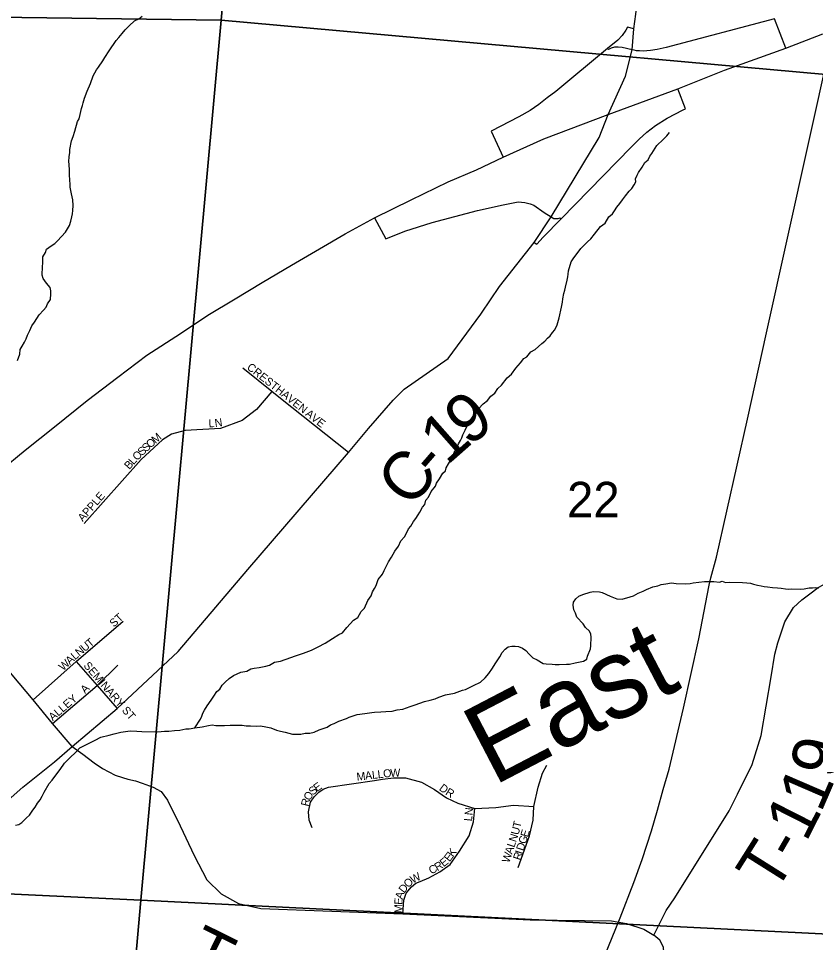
# Model space of a CAD drawing. Extents: x 1310247 to 1552180, y 377264 to 706493.
# Drawn here: x 1428492 to 1433472, y 489060 to 494835 of the extents above; entities that cross this region are included whole.
import ezdxf

# ---------------------------------------------------------------- set-up
doc = ezdxf.new("R2010")
doc.units = 0
for name, color, linetype in [('GM_X_County_Road', 7, 'Continuous'), ('GM_X_County_Road_Text', 7, 'Continuous'), ('GM_X_Interchange_Ramps', 7, 'Continuous'), ('GM_X_Interstate_Route', 7, 'Continuous'), ('GM_X_Minor_River', 7, 'Continuous'), ('GM_X_Minor_River_Text', 7, 'Continuous'), ('GM_X_Rail_Line', 7, 'Continuous'), ('GM_X_Section', 7, 'Continuous'), ('GM_X_Section_Text', 7, 'Continuous'), ('GM_X_Township_Road', 7, 'Continuous'), ('GM_X_Township_Road_Text', 7, 'Continuous'), ('GM_X_Township_Subdivision', 7, 'Continuous'), ('GM_X_Township_Subdivision_Text', 7, 'Continuous')]:
    doc.layers.add(name, color=color, linetype=linetype)

msp = doc.modelspace()

# ---------------------------------------------------------------- linework, layer by layer
at = {"layer": 'GM_X_County_Road'}
for points in [[(1431381.6, 492987.5), (1431385.2, 492992.3), (1431497.9, 493159), (1431713.4, 493434.6), (1431820.6, 493596.1), (1432120.9, 494091.1), (1432177.2, 494235.8), (1432285.4, 494474.8), (1432325.4, 494638.3), (1432336.7, 494770.6), (1432349.4, 494862.8), (1432380, 495160.6), (1432473.4, 496205.1), (1432525.8, 496791), (1432540.5, 496955.1), (1432582.1, 497292.2), (1432617.5, 497731.2), (1432712.9, 500020.8)], [(1429724.6, 491155.6), (1429924.8, 491390.6), (1430553.7, 492122.3), (1430678.1, 492272.1), (1430832.5, 492450.4), (1430902, 492518.3), (1431177.2, 492710), (1431381.6, 492987.5)], [(1428071.5, 488432.1), (1428071.5, 488432.1), (1428109.7, 488932), (1428113, 489124.6), (1428157.6, 489517.4), (1428185.3, 489642.2), (1428252.3, 489770.7), (1428370.4, 489902.4), (1428519, 490030.4), (1428716.9, 490189.5), (1428826.6, 490284.9), (1429108.1, 490523.8), (1429489.4, 490879.6), (1429724.6, 491155.6)]]:
    msp.add_lwpolyline(points, dxfattribs=at)
at = {"layer": 'GM_X_Interchange_Ramps'}
for points in [[(1433286.5, 494649.5), (1433214.7, 494832.9), (1432537.7, 494652.8), (1432483.3, 494640.6), (1432440.2, 494634.7), (1432394.3, 494631.6), (1432372.6, 494631.7), (1432353.3, 494633.2), (1432338.7, 494636.7), (1432325.4, 494638.3)], [(1432336.7, 494770.6), (1432296.1, 494780.5), (1432287.7, 494761.4), (1432264.8, 494727.5), (1432235.9, 494699.2), (1432173.1, 494647.1), (1431848.9, 494378.4), (1431794.6, 494338.9), (1431742.8, 494298.3), (1431688, 494260.4), (1431618.6, 494219.3), (1431444.5, 494130.2), (1431520.9, 493968.9)], [(1432325.4, 494638.3), (1432264.3, 494653.2), (1432237.8, 494656.2), (1432216.2, 494654.6), (1432196.1, 494648.8), (1432178.4, 494640.7), (1432173.1, 494647.1)], [(1431713.4, 493434.6), (1431730, 493423.8), (1431769.6, 493467.4), (1431881.7, 493582.3), (1432319.1, 494031), (1432370.4, 494080.3), (1432418.5, 494123.7), (1432471.5, 494165.7), (1432545.2, 494211.9), (1432645.1, 494263.5), (1432660.4, 494270.3), (1432610.9, 494395.8)], [(1430717.3, 493588.9), (1430787.5, 493457.1), (1430906.9, 493504.8), (1431077.2, 493559.6), (1431360.9, 493635.5), (1431520.8, 493669.6), (1431615, 493688.8), (1431656.5, 493685.2), (1431688.7, 493676.9), (1431712.7, 493667.3), (1431776.8, 493622.6), (1431820.6, 493596.1)], [(1431820.6, 493596.1), (1431837.3, 493585.9), (1431846.2, 493584.1), (1431856.5, 493584.3), (1431864.4, 493585.1), (1431874.6, 493589.2), (1431881.7, 493582.3)]]:
    msp.add_lwpolyline(points, dxfattribs=at)
at = {"layer": 'GM_X_Interstate_Route'}
for points in [[(1432177.2, 494235.8), (1432610.9, 494395.8), (1432903.4, 494511.1), (1433286.5, 494649.5), (1433516.8, 494739.6)], [(1428377.8, 492008.3), (1428533.6, 492136.5), (1428717.5, 492282.4), (1428921.8, 492448.1), (1429111.8, 492594), (1429293.7, 492729.9), (1429503.6, 492865.5), (1429675.2, 492981.5), (1429846.6, 493083.5), (1430014, 493185.5), (1430197.6, 493293.4), (1430373, 493395.3), (1430532.3, 493489.5), (1430717.3, 493588.9), (1430945.3, 493700.6), (1431177, 493813.8), (1431354.1, 493889.7), (1431520.9, 493968.9), (1431774.9, 494082.7), (1432177.2, 494235.8)]]:
    msp.add_lwpolyline(points, dxfattribs=at)
at = {"layer": 'GM_X_Minor_River'}
for points in [[(1428486, 492698.5), (1428500.8, 492736.3), (1428503.4, 492766.4), (1428515.8, 492786.2), (1428530.3, 492812), (1428540.7, 492831.9), (1428549.1, 492855.8), (1428563.7, 492885.6), (1428576.3, 492913.5), (1428592.7, 492937.2), (1428621.6, 492982.8), (1428648.1, 493012.4), (1428664.5, 493030.1), (1428672.9, 493052), (1428691.4, 493077.7), (1428694.1, 493113.8), (1428694.5, 493131.9), (1428689, 493154.1), (1428667.6, 493180.7), (1428646.2, 493209.2), (1428640.6, 493231.4), (1428641.7, 493285.6), (1428644.1, 493305.7), (1428645, 493345.8), (1428661.5, 493371.6), (1428667.9, 493393.5), (1428696.3, 493415), (1428718.5, 493428.6), (1428734.8, 493446.3), (1428761.3, 493471.9), (1428785.8, 493499.5), (1428810.6, 493541.2), (1428819.2, 493569.1), (1428825.7, 493595.1), (1428830.1, 493615.1), (1428832.5, 493635.1), (1428833.2, 493667.2), (1428831.9, 493701.4), (1428822.7, 493739.7), (1428815.5, 493780), (1428814, 493802.2), (1428812.4, 493822.3), (1428811.2, 493860.5), (1428809.7, 493886.6), (1428808.4, 493922.8), (1428806.8, 493940.9), (1428809.4, 493970.9), (1428811.9, 493997), (1428812.3, 494015.1), (1428823.4, 494071), (1428833.9, 494096.9), (1428844.6, 494130.9), (1428859.8, 494190.8), (1428870.2, 494208.6), (1428876.7, 494234.6), (1428885.4, 494272.6), (1428891.8, 494290.5), (1428896.2, 494308.5), (1428904.7, 494336.5), (1428921.6, 494380.3), (1428942.5, 494428), (1428959.5, 494475.9), (1428980.2, 494513.6), (1428992.5, 494531.4), (1429019.3, 494571), (1429031.7, 494590.9), (1429058.5, 494632.5), (1429101.7, 494697.8), (1429118.1, 494715.6), (1429140.5, 494741.2), (1429158.9, 494762.9), (1429183.4, 494788.5), (1429216, 494820), (1429244.2, 494833.5), (1429264.5, 494849.1)], [(1431796.6, 492836.5), (1431814.9, 492852.2), (1431829.3, 492872), (1431843.6, 492889.7), (1431858.2, 492919.5), (1431871, 492963.5), (1431884.4, 493031.5), (1431891, 493061.4), (1431893.5, 493083.5), (1431900.1, 493115.5), (1431906.5, 493137.4), (1431908.9, 493155.5), (1431919.8, 493199.4), (1431924.2, 493219.4), (1431926.5, 493237.4), (1431928.9, 493257.5), (1431946.1, 493313.3), (1431962.6, 493339.1), (1431989.2, 493374.7), (1432005.7, 493398.4), (1432046.4, 493439.8), (1432068.8, 493457.4), (1432091.3, 493487), (1432128.2, 493534.5), (1432156.6, 493556), (1432181.4, 493595.6), (1432203.7, 493613.2), (1432216.1, 493633), (1432230.5, 493654.8), (1432248.9, 493678.5), (1432265.4, 493702.3), (1432283.9, 493726), (1432308.4, 493755.6), (1432324.7, 493773.4), (1432339.2, 493795.1), (1432349.5, 493815), (1432347.9, 493833.1), (1432358.3, 493855), (1432366.7, 493872.9), (1432389.3, 493906.6), (1432405.9, 493934.3), (1432426.2, 493952), (1432436.6, 493973.8), (1432449, 493991.7), (1432479.9, 494041.2), (1432520.6, 494078.5), (1432543, 494102.2), (1432559.4, 494121.9)], [(1429593.1, 490402.2), (1429630.1, 490455.6), (1429636.5, 490475.6), (1429642.9, 490493.5), (1429653.2, 490511.4), (1429671.8, 490539.1), (1429696.4, 490574.7), (1429712.9, 490600.5), (1429731.5, 490628.2), (1429749.7, 490643.9), (1429764.2, 490667.7), (1429782.6, 490687.4), (1429809, 490711), (1429835.3, 490728.5), (1429881.6, 490749.6), (1429917.7, 490756.9), (1429944, 490770.4), (1429964, 490774), (1429996, 490779.4), (1430038.1, 490786.5), (1430060.2, 490794.1), (1430092.5, 490811.5), (1430128.6, 490818.8), (1430192.9, 490841.5), (1430223.1, 490851), (1430273.3, 490868), (1430323.6, 490887), (1430364, 490908.3), (1430408.4, 490931.5), (1430452.9, 490960.6), (1430493.3, 490985.9), (1430517.4, 490995.5), (1430544.1, 491029), (1430584.9, 491074.4), (1430611.2, 491091.9), (1430634, 491129.6), (1430654.3, 491149.2), (1430675.3, 491197), (1430695.8, 491226.7), (1430704.3, 491252.6), (1430716.7, 491272.5), (1430727.1, 491292.3), (1430739.8, 491328.2), (1430766.5, 491361.8), (1430776.9, 491385.7), (1430789.4, 491409.5), (1430804, 491439.3), (1430822.5, 491469.1), (1430843.3, 491506.8), (1430865.8, 491536.5), (1430880.5, 491570.3), (1430903, 491595.9), (1430913.3, 491613.8), (1430927.9, 491645.6), (1430944.3, 491663.3), (1430960.8, 491691.1), (1430975.2, 491710.9), (1430989.6, 491732.7), (1430999.9, 491750.5), (1431016.5, 491780.3), (1431030.8, 491798.1), (1431037.4, 491824.1), (1431053.7, 491843.8), (1431070.4, 491879.6), (1431097.1, 491913.2), (1431103.4, 491931.1), (1431121.9, 491958.9), (1431142.6, 491992.6), (1431160.9, 492008.3), (1431163.3, 492026.3), (1431194.2, 492075.8), (1431206.6, 492097.7), (1431215.1, 492121.6), (1431225.4, 492139.5), (1431242.2, 492177.3), (1431254.6, 492197.1), (1431262.9, 492215), (1431269.3, 492232.9), (1431281.9, 492262.8), (1431302.6, 492302.5), (1431333.5, 492350.1), (1431362, 492377.6), (1431366.4, 492395.6), (1431395, 492427.1), (1431423.3, 492446.6), (1431443.9, 492474.3), (1431468.2, 492493.9), (1431486.8, 492521.6), (1431509.2, 492543.2), (1431546, 492588.6), (1431572.4, 492612.2), (1431599.2, 492649.8), (1431627.8, 492683.3), (1431650.3, 492709), (1431668.5, 492720.7), (1431693.1, 492752.3), (1431719.3, 492765.8), (1431741.7, 492785.4), (1431762, 492803.1), (1431780.3, 492818.8), (1431796.6, 492836.5)], [(1431430.5, 490741.5), (1431453.2, 490775.2), (1431469.7, 490801), (1431498.6, 490846.5), (1431513.1, 490872.3), (1431533.5, 490894), (1431551.7, 490907.7), (1431573.8, 490913.2), (1431595.7, 490912.8), (1431615.6, 490910.4), (1431641.4, 490899.8), (1431661, 490885.3), (1431682.5, 490862.8), (1431706, 490840.2), (1431733.7, 490827.6), (1431771.2, 490804.7), (1431789.1, 490802.3), (1431827, 490799.5), (1431844.9, 490797.2), (1431870.9, 490798.6), (1431916.8, 490799.7), (1431934.8, 490799.3), (1431970.9, 490808.6), (1432023, 490819.6), (1432043.2, 490831.2), (1432047.6, 490849.2), (1432066.5, 490895), (1432068.9, 490915), (1432070, 490969.2), (1432068.3, 490987.3), (1432058.7, 491005.6), (1432035.2, 491028.2), (1432019.8, 491052.6), (1431980.7, 491093.6), (1431971.2, 491117.9), (1431961.7, 491140.1), (1431958.2, 491168.3), (1431960.6, 491186.4), (1431975, 491208.1), (1431993.3, 491223.8), (1432017.5, 491235.4), (1432063.7, 491250.5), (1432085.7, 491254), (1432121.6, 491251.3), (1432139.5, 491246.9), (1432188.9, 491223.8), (1432230.5, 491208.9), (1432264.4, 491206.1), (1432314.6, 491221.2), (1432334.7, 491226.8), (1432363, 491244.3), (1432395.2, 491255.6), (1432415.4, 491267.3), (1432455.6, 491282.5), (1432485.7, 491289.9), (1432507.8, 491297.5), (1432535.8, 491300.9), (1432571.9, 491308.2), (1432601.8, 491303.6), (1432659.6, 491302.4), (1432689.6, 491303.8), (1432707.7, 491307.4), (1432777.7, 491316), (1432795.7, 491315.6), (1432813.7, 491317.2), (1432835.6, 491316.8), (1432871.4, 491312), (1432889.5, 491317.7), (1432909.4, 491311.2), (1432933.3, 491312.7), (1433015.1, 491311), (1433043, 491308.5), (1433065, 491306), (1433084.8, 491299.5), (1433108.6, 491293), (1433132.5, 491288.5), (1433150.4, 491286.1), (1433172.3, 491283.7), (1433202.1, 491279), (1433234, 491276.4), (1433257.9, 491273.8), (1433283.8, 491271.3), (1433305.7, 491268.8), (1433323.7, 491270.5), (1433377.6, 491269.4), (1433401.6, 491270.9), (1433431.7, 491276.3), (1433453.6, 491277.8), (1433471.6, 491279.5), (1433491.6, 491277)], [(1428472.9, 489794.8), (1428494.9, 489798.4), (1428513.1, 489810.1), (1428541.7, 489839.6), (1428560, 489857.3), (1428582.6, 489887), (1428596.9, 489906.7), (1428611.4, 489930.5), (1428627.8, 489952.3), (1428640.2, 489974.1), (1428652.7, 490000), (1428683.7, 490053.5), (1428702.2, 490075.3), (1428730.9, 490114.8), (1428753.4, 490142.5), (1428780.2, 490182.1), (1428806.7, 490207.6), (1428855.6, 490256.8), (1428875.9, 490276.5), (1428916.3, 490297.7), (1428938.4, 490307.3), (1428970.7, 490324.7), (1429007.1, 490344), (1429059.2, 490357), (1429089.3, 490364.4), (1429131.5, 490375.6), (1429189.5, 490382.4), (1429231.4, 490381.6), (1429263.3, 490378.9), (1429363, 490376.8), (1429405.1, 490382), (1429431, 490381.4), (1429467, 490384.7), (1429501, 490388), (1429537.1, 490395.3), (1429559.1, 490396.8), (1429593.1, 490402.2), (1429639.2, 490409.2), (1429679.2, 490416.4), (1429701.3, 490420), (1429725.2, 490417.5), (1429779.1, 490416.4), (1429815.1, 490419.6), (1429888.9, 490418.1), (1429914.8, 490415.5), (1429940.7, 490415), (1429978.6, 490412.2), (1430004.6, 490413.7), (1430036.4, 490409), (1430068.2, 490402.3), (1430103.8, 490387.5), (1430129.7, 490381), (1430157.5, 490374.4), (1430181.3, 490367.8), (1430203.2, 490363.4), (1430257, 490362.2), (1430283.1, 490367.7), (1430313.1, 490369.1), (1430339.1, 490374.6), (1430371.4, 490390), (1430401.5, 490399.4), (1430421.6, 490407), (1430441.9, 490420.7), (1430464, 490428.2), (1430494.2, 490443.7), (1430540.5, 490460.8), (1430558.6, 490468.4), (1430608.9, 490485.5), (1430656.9, 490492.5), (1430699, 490497.7), (1430717, 490499.3), (1430756.9, 490502.5), (1430786.9, 490503.9), (1430826.9, 490507), (1430859, 490514.4), (1430893, 490519.7), (1430939.3, 490534.8), (1430971.4, 490546.2), (1431027.8, 490567.1), (1431063.8, 490574.4), (1431096, 490583.8), (1431118.1, 490593.4), (1431160.3, 490608.6), (1431216.5, 490619.5), (1431266.7, 490636.5), (1431284.8, 490642.1), (1431309, 490653.7), (1431335.2, 490667.2), (1431379.5, 490688.3), (1431408, 490713.9), (1431430.5, 490741.5)]]:
    msp.add_lwpolyline(points, dxfattribs=at)
at = {"layer": 'GM_X_Rail_Line'}
msp.add_lwpolyline([(1432127.7, 488911.9), (1432252.3, 489215.5), (1432336.2, 489435.2), (1432387.9, 489580.1), (1432446.1, 489759.1), (1432483.9, 489886.5), (1432520.8, 490016.6), (1432556.8, 490144), (1432646.4, 490524.2), (1432742.3, 490958), (1432806.9, 491293), (1432817.1, 491339.2), (1432853.1, 491469.3), (1433046, 492330.4), (1433166, 492869.4), (1433693.9, 495257.9)], dxfattribs=at)
at = {"layer": 'GM_X_Section'}
for points in [[(1430245.7, 500293), (1429758, 494823.6), (1424307.8, 494896.9), (1424746.1, 500303.3)], [(1430245.7, 500293), (1435471.2, 499726.6), (1434995.6, 494353), (1429758, 494823.6)], [(1429758, 494823.6), (1429255.8, 489324.6), (1423863.5, 489580.6), (1424307.8, 494896.9)], [(1429758, 494823.6), (1434995.6, 494353), (1434523.9, 489065.4), (1429255.8, 489324.6)], [(1423863.5, 489580.6), (1429255.8, 489324.6), (1428777.4, 483907.1), (1423391.5, 484184.8)], [(1434523.9, 489065.4), (1433994.3, 483685), (1428777.4, 483907.1), (1429255.8, 489324.6)]]:
    msp.add_lwpolyline(points, close=True, dxfattribs=at)
at = {"layer": 'GM_X_Township_Road'}
for points in [[(1428826.6, 490284.9), (1428705.1, 490428.4), (1428584, 490576.2), (1428453.1, 490733.5), (1428166.9, 491109.6), (1427837.1, 491506.3), (1427605.8, 491826.7), (1427337.7, 492126.1), (1427304, 492161.9)], [(1433194.5, 490721.5), (1433218.4, 490862.8), (1433236.7, 490932.4), (1433279.3, 491065), (1433335.2, 491155), (1433387.3, 491201.4), (1433435.6, 491239.3), (1433487.7, 491279.1), (1433581.5, 491328.4), (1433702.3, 491387), (1433702.7, 491387.2)], [(1432261.9, 487803.1), (1432291.4, 487909.7), (1432353.6, 488165.6), (1432478.8, 488765.2), (1432524.7, 488999.1), (1432522.4, 489030.8), (1432499.8, 489074.4), (1432460.7, 489105.6), (1432539.4, 489260.2), (1432592.1, 489340), (1432933, 489883.1), (1432984.5, 489987.3), (1433076.6, 490173.6), (1433132.5, 490354.6), (1433194.5, 490721.5)], [(1428826.6, 490284.9), (1428893.7, 490238), (1428965.2, 490182.9), (1429017.8, 490147.1), (1429095.8, 490107), (1429142.8, 490091.5), (1429174.5, 490081.5), (1429222.4, 490069.9), (1429264.8, 490056), (1429333.5, 490031.3), (1429383.7, 490003.5), (1429423.1, 489949.5), (1429460.7, 489873.6)], [(1429460.7, 489873.6), (1429484.8, 489825.2), (1429589, 489604.4), (1429669.3, 489452.4), (1429758, 489364.4), (1429867.6, 489303.7), (1430006.6, 489273.3), (1430892.7, 489239.4), (1431690, 489201.4), (1432196.2, 489195.6), (1432291.4, 489178.6), (1432399.6, 489144.6), (1432460.7, 489105.6)]]:
    msp.add_lwpolyline(points, dxfattribs=at)
at = {"layer": 'GM_X_Township_Subdivision'}
for points in [[(1430553.7, 492122.3), (1430129.7, 492460.4), (1430075.5, 492502.9), (1429892.8, 492650.1)], [(1430075.5, 492502.9), (1429979.3, 492391.9), (1429890.5, 492323.4), (1429753.6, 492271.6), (1429533.5, 492260.5), (1429448.4, 492236.4), (1429391, 492201.3), (1429257.8, 492079.2), (1428902.7, 491679.5)], [(1428584, 490576.2), (1428853, 490817), (1429146.2, 491068.3)], [(1428705.1, 490428.4), (1428983.4, 490667.1), (1429112.3, 490793.8)], [(1428853, 490817), (1428983.4, 490667.1), (1429108.1, 490523.8)], [(1431614.4, 489528.3), (1431684.8, 489726.8), (1431708.7, 489826), (1431711.1, 489909.6), (1431738.8, 490032.1), (1431766.4, 490118.8), (1431792.8, 490167.8)], [(1430326, 489777), (1430307.2, 489826), (1430303.4, 489877.5), (1430317.3, 489937.8), (1430339.9, 489971.8), (1430368.8, 489999.4), (1430396.4, 490018.2), (1430429.7, 490030.2), (1430715.5, 490072.9), (1430767, 490081.1), (1430836.1, 490089.9), (1430909.9, 490090.1), (1431010.1, 490062.2), (1431090.5, 490015.8), (1431166.7, 489965.5), (1431237.5, 489930.3), (1431343.7, 489898.9), (1431473.7, 489905.2), (1431584.3, 489919), (1431711.1, 489909.6)], [(1430892.7, 489239.4), (1430899.2, 489324.9), (1430913.5, 489369), (1430946.7, 489407.7), (1430974.3, 489430.9), (1431001.7, 489442.5), (1431056, 489464), (1431125.5, 489502.6), (1431188.7, 489547.9), (1431248.1, 489631.8), (1431308.8, 489727.8), (1431335.5, 489814.7), (1431343.7, 489898.9)]]:
    msp.add_lwpolyline(points, dxfattribs=at)

# ---------------------------------------------------------------- texts
at = {"layer": 'GM_X_County_Road_Text'}
for s, rotation, p in [('9', 36.86798, (1431301.7, 492155.6)), ('1', 41.44431, (1431169.2, 492038.3)), ('C', 49.88296, (1430940, 491767.2)), ('-', 49.18472, (1431096.9, 491953.5))]:
    msp.add_text(s, height=300, rotation=rotation, dxfattribs=at).set_placement(p)
at = {"layer": 'GM_X_Minor_River_Text'}
msp.add_text('East', height=499.98, rotation=27.53796, dxfattribs=at).set_placement((1431457.5, 490035.6))
at = {"layer": 'GM_X_Section_Text'}
msp.add_text('22', height=221, rotation=0.00001, dxfattribs=at).set_placement((1431919.5, 491718.1))
at = {"layer": 'GM_X_Township_Road_Text'}
for s, rotation, p in [('9', 74.43159, (1433593.5, 490077.5)), ('1', 66.64619, (1433505.4, 489866)), ('1', 63.05237, (1433412.9, 489682.7)), ('T', 57.81608, (1433217, 489360.1)), ('-', 59.96738, (1433342.9, 489560.5)), ('T', 333.60457, (1429518.8, 488908.2))]:
    msp.add_text(s, height=300, rotation=rotation, dxfattribs=at).set_placement(p)
at = {"layer": 'GM_X_Township_Subdivision_Text'}
for s, rotation, p in [('CRESTHAVEN', 321.6338, (1429914.8, 492647.3)), ('L', 2.18632, (1429680.4, 492279.9)), ('N', 7.84962, (1429720.9, 492281.7)), ('AVE', 321.95437, (1430279.7, 492357.1)), ('M', 39.95132, (1429348.3, 492175.4)), ('S', 42.18824, (1429263.6, 492099.3)), ('S', 41.86839, (1429289.7, 492122.9)), ('O', 41.86861, (1429315.9, 492146.4)), ('O', 45.90422, (1429233.6, 492068.3)), ('B', 48.47939, (1429184.5, 492012.7)), ('L', 48.46968, (1429210.7, 492042.4)), ('APPLE', 48.81189, (1428894, 491687.1)), ('ST', 42.50715, (1429088.4, 491027.9)), ('T', 39.6027, (1428939.4, 490902.5)), ('N', 39.66004, (1428871.6, 490846.3)), ('U', 39.61388, (1428905.5, 490874.4)), ('W', 43.21064, (1428771.5, 490755)), ('A', 42.77364, (1428813.1, 490794.1)), ('L', 40.48423, (1428845, 490823.6)), ('SEMINARY ST', 310.6004, (1428895.2, 490789.3)), ('A', 45, (1428908.1, 490613.5)), ('ALLEY', 40.60026, (1428706.2, 490442.4)), ('L', 6.55938, (1430738.2, 490086.1)), ('O', 6.5381, (1430773.1, 490090.1)), ('W', 2.47239, (1430815.9, 490095)), ('M', 6.54436, (1430607, 490071)), ('A', 6.5381, (1430659.5, 490077.1)), ('L', 6.5404, (1430703.2, 490082.1)), ('S', 41.8491, (1430331.8, 489977.3)), ('E', 36.00929, (1430356.9, 489999.9)), ('D', 323.52351, (1431115.8, 490016.2)), ('R', 328.46483, (1431155.1, 489987.5)), ('O', 58.97814, (1430311.6, 489942.6)), ('R', 76.64406, (1430304, 489907.9)), ('LN', 83.99458, (1431325, 489816.3)), ('T', 76.61939, (1431627.3, 489772.9)), ('N', 71.65348, (1431600.9, 489684.1)), ('U', 75.14244, (1431615.7, 489729)), ('E', 74.16105, (1431674.8, 489715.4)), ('L', 71.63564, (1431589.8, 489650.7)), ('D', 71.74243, (1431647.2, 489629.5)), ('G', 72.61532, (1431661.2, 489672.1)), ('E', 52.85965, (1431185.4, 489561.5)), ('K', 54.96653, (1431207.8, 489591.1)), ('W', 71.64745, (1431557.9, 489554.6)), ('A', 71.64453, (1431575.9, 489608.9)), ('R', 71.56889, (1431627.7, 489570.9)), ('I', 71.57186, (1431640.2, 489608.4)), ('R', 31.52986, (1431109.2, 489505.2)), ('E', 38.60406, (1431148.4, 489529.8)), ('W', 27.48994, (1430955.3, 489427.7)), ('C', 27.50459, (1431070.7, 489485)), ('O', 44.88409, (1430927.3, 489399)), ('D', 52.69729, (1430901.8, 489365.3)), ('E', 87.67717, (1430890.1, 489295.6)), ('A', 72.85066, (1430891, 489327.4)), ('M', 89.09841, (1430889.3, 489243.1))]:
    msp.add_text(s, height=50, rotation=rotation, dxfattribs=at).set_placement(p)

doc.saveas('drawing.dxf')
